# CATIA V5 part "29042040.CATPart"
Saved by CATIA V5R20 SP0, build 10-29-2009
Part number: 29042040
Definition: NONE
Nomenclature: 29042040
Source: Unknown
Description: 29042040
Bounding box of the stored display mesh (mm): x -20 to 44.548, y -35 to 69.548, z -25 to 25
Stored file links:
  C:\Users\Utente\Desktop\IO LAVORO\3D X SITO CF\X SITO\PLASTICA\RF1\29042040.CATPart
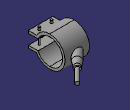
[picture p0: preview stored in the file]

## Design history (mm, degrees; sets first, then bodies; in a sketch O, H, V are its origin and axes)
Body1 "29042040" (main body)
  Solid1: solid without history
